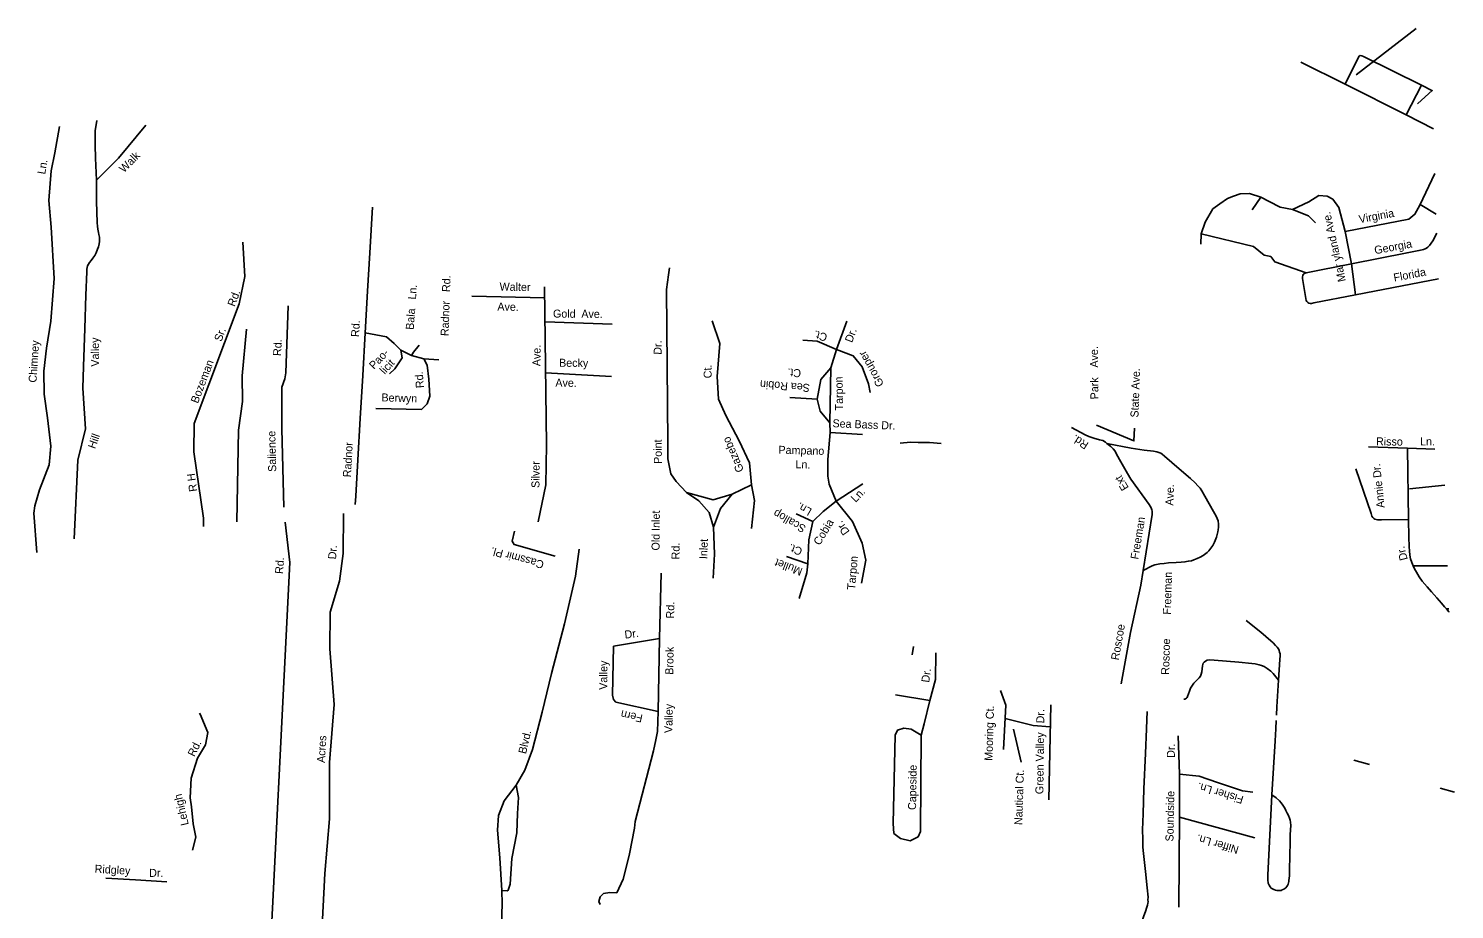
# Model space of a CAD drawing. Extents: x 2308163 to 2335412, y -96774 to 127732.
# Drawn here: x 2321661.2 to 2322026.5, y 52675.9 to 52901.5 of the extents above; entities that cross this region are included whole.
import ezdxf

# ---------------------------------------------------------------- set-up
doc = ezdxf.new("R2010")
doc.units = 0
doc.layers.add('Old_Level_10', color=7, linetype='Continuous')
doc.layers.add('Old_Level_35', color=7, linetype='Continuous')

msp = doc.modelspace()

# ---------------------------------------------------------------- linework, layer by layer
at = {"layer": 'Old_Level_10'}
for points in [[(2322016.66, 52901.47), (2322001.3, 52889.64)], [(2322020.83, 52885.72), (2322017.03, 52882.22)], [(2321944.49, 52799.11), (2321944.38, 52795.89), (2321934.83, 52799.93)], [(2321915.47, 52713.63), (2321913.5, 52722.08)]]:
    msp.add_lwpolyline(points, dxfattribs=at)
at = {"layer": 'Old_Level_35'}
for p, q in [((2321987.14, 52892.82), (2321998.45, 52887.22)), ((2321998.45, 52887.22), (2322014.14, 52879.35)), ((2322014.14, 52879.35), (2322018.07, 52886.93)), ((2322020.84, 52885.55), (2322018.07, 52886.93)), ((2322021.14, 52875.83), (2322014.14, 52879.35)), ((2322001.15, 52833.32), (2322000.08, 52841.23)), ((2322014.71, 52775.78), (2322014.44, 52794)), ((2321706, 52776.1), (2321703.58, 52793.06)), ((2321744.9, 52779.59), (2321745.02, 52781.74)), ((2321706.01, 52773.96), (2321706, 52776.1)), ((2321887.58, 52741.13), (2321887.87, 52743.25)), ((2321980.99, 52727.77), (2321981.38, 52734.62)), ((2321980.87, 52725.66), (2321980.99, 52727.77)), ((2321947.58, 52722.18), (2321947.67, 52724.47)), ((2321947.67, 52724.47), (2321947.75, 52726.6)), ((2321980.78, 52724.25), (2321980.69, 52722.14)), ((2321980.69, 52722.14), (2321980.56, 52719.06)), ((2321980.56, 52719.06), (2321979.74, 52705.27)), ((2322004.75, 52713.05), (2322000.7, 52714.08)), ((2322026.5, 52705.96), (2322022.86, 52706.99))]:
    msp.add_line(p, q, dxfattribs=at)
for points in [[(2322018.07, 52886.93), (2322003.18, 52894.3), (2322002.74, 52894.52), (2322002.37, 52894.58), (2322002.06, 52894.4), (2322001.93, 52894.14), (2321998.45, 52887.22)], [(2321678.62, 52862.63), (2321678.39, 52868.27), (2321678.28, 52871.58), (2321678.24, 52872.95), (2321678.3, 52875.27), (2321678.68, 52877.88)], [(2321667.96, 52869.61), (2321669.14, 52876.38)], [(2321691.28, 52876.77), (2321684.26, 52868.24), (2321678.62, 52862.63)], [(2321663.29, 52767.31), (2321662.56, 52777.37), (2321662.78, 52779.27), (2321664.03, 52783.34), (2321666.47, 52789.76), (2321666.95, 52794.5), (2321666.1, 52801.82), (2321665.19, 52807.88), (2321665.08, 52813.75), (2321665.76, 52819.59), (2321666.95, 52826.52), (2321667.8, 52837.43), (2321666.99, 52850.62), (2321666.43, 52857.45), (2321667.01, 52865.04), (2321667.96, 52869.61)], [(2321675.15, 52809.36), (2321675.28, 52814.94), (2321675.58, 52824.68), (2321675.85, 52833.23), (2321676.13, 52839.17), (2321676.13, 52839.87), (2321676.18, 52840.29), (2321676.28, 52840.74), (2321676.55, 52841.16), (2321676.82, 52841.53), (2321677.25, 52842.09), (2321677.71, 52842.7), (2321678.15, 52843.36), (2321678.5, 52844.04), (2321678.89, 52844.98), (2321679.09, 52845.61), (2321679.26, 52846.33), (2321679.35, 52846.98), (2321679.34, 52847.51), (2321679.34, 52848.04), (2321679.25, 52848.7), (2321679.15, 52849.23), (2321678.95, 52850.07), (2321678.84, 52850.83), (2321678.74, 52851.69), (2321678.62, 52857.25), (2321678.62, 52862.63)], [(2322017.62, 52856.24), (2322021.5, 52864.36)], [(2322000.08, 52841.23), (2321998.49, 52849.48), (2321996.84, 52855.63), (2321995.33, 52857.81), (2321993.89, 52858.52), (2321991.78, 52858.73), (2321989.2, 52857.09), (2321985.02, 52855.11), (2321981.85, 52855.75), (2321978.98, 52857.18), (2321976.9, 52858.31), (2321974.01, 52859.21), (2321971.62, 52859.16), (2321969.87, 52858.55), (2321968.39, 52857.94), (2321966.35, 52856.55), (2321964.59, 52855.29), (2321962.61, 52851.91), (2321961.58, 52848.89), (2321961.49, 52846.24)], [(2321745.02, 52781.74), (2321745.56, 52791.03), (2321746.18, 52801.65), (2321746.83, 52812.64), (2321747.46, 52823.56), (2321748.04, 52834.24), (2321748.65, 52844.04), (2321749.3, 52855.74)], [(2321976.9, 52858.31), (2321974.66, 52855.07)], [(2321998.49, 52849.48), (2322014.84, 52852.63), (2322016.35, 52853.9), (2322017.62, 52856.24)], [(2322021.83, 52853.92), (2322017.7, 52856.4)], [(2321985.02, 52855.11), (2321989.07, 52853.51), (2321990.87, 52851.73)], [(2321961.58, 52848.89), (2321975, 52845.64), (2321977.71, 52843.43), (2321979.43, 52843.11), (2321980.44, 52841.74), (2321988.54, 52838.89)], [(2322000.08, 52841.23), (2322014.35, 52844.07), (2322017.37, 52844.62), (2322018.19, 52844.79), (2322018.56, 52844.9), (2322019, 52845.09), (2322019.29, 52845.26), (2322019.64, 52845.5), (2322020.06, 52845.9), (2322020.53, 52846.48), (2322020.92, 52847.1), (2322021.99, 52849.06)], [(2321703.58, 52793.06), (2321703.64, 52800.31), (2321715.19, 52830.99), (2321716.58, 52838), (2321716.12, 52846.78)], [(2322001.15, 52833.32), (2321990.47, 52831.21), (2321989.83, 52831.09), (2321989.56, 52831.09), (2321989.22, 52831.17), (2321988.96, 52831.3), (2321988.66, 52831.55), (2321988.47, 52831.87), (2321987.56, 52837.46), (2321987.56, 52837.89), (2321987.63, 52838.21), (2321987.77, 52838.52), (2321987.89, 52838.66), (2321988.22, 52838.83), (2321988.54, 52838.89), (2322000.08, 52841.23)], [(2321836.58, 52760.75), (2321836.97, 52766.88), (2321836.67, 52773.75), (2321835.53, 52777.58), (2321832.93, 52780.56), (2321829.75, 52782.65), (2321827.13, 52785.45), (2321825.76, 52787.48), (2321824.99, 52791.3), (2321824.95, 52795.46), (2321824.67, 52834.64), (2321825.17, 52838.41), (2321825.41, 52840.21)], [(2322022.36, 52837.36), (2322013.09, 52835.59), (2322001.15, 52833.32)], [(2321791.76, 52775.12), (2321793.72, 52784.62), (2321793.89, 52794.9), (2321793.4, 52835.3)], [(2321726.57, 52778.9), (2321726.08, 52798.96), (2321726.09, 52809.61), (2321726.89, 52811.75), (2321727.12, 52813.27), (2321727.71, 52830.49)], [(2321774.79, 52832.93), (2321793.44, 52832.48)], [(2321793.51, 52826.33), (2321810.68, 52825.74)], [(2321846.43, 52784.6), (2321845.9, 52790.22), (2321843.21, 52795.91), (2321839.82, 52802.34), (2321837.98, 52806.56), (2321837.64, 52812.35), (2321838.29, 52820.81), (2321836.32, 52826.66)], [(2321868.11, 52780.43), (2321866.28, 52784.82), (2321865.99, 52786.82), (2321865.95, 52791.15), (2321866.55, 52797.99), (2321866.46, 52800.52), (2321866.76, 52814.59), (2321868.19, 52819.24), (2321870.79, 52826.55)], [(2321714.54, 52775.18), (2321714.96, 52798.62), (2321716.03, 52805.98), (2321715.9, 52812.58), (2321717.03, 52824.45)], [(2321747.46, 52823.56), (2321752.93, 52822.49), (2321754.86, 52820.8), (2321756.61, 52819.12), (2321756.9, 52817.12), (2321755, 52814.3), (2321753.69, 52813.08)], [(2321756.61, 52819.12), (2321759.27, 52817.76), (2321759.84, 52818.64), (2321761.31, 52820.42)], [(2321868.19, 52819.24), (2321863.2, 52821.4), (2321859.6, 52821.7)], [(2321868.19, 52819.24), (2321872.47, 52817.65), (2321874.72, 52814.86), (2321876.38, 52810.47), (2321876.84, 52808.29)], [(2321762.49, 52816.93), (2321763.34, 52815.27), (2321763.76, 52811.65), (2321763.97, 52807.31), (2321763.36, 52805.34), (2321761.87, 52803.95), (2321750.13, 52804.17)], [(2321759.27, 52817.76), (2321762.49, 52816.93), (2321766.28, 52816.62)], [(2321793.67, 52813.33), (2321810.57, 52812.37)], [(2321866.76, 52814.59), (2321864.13, 52811.62), (2321863.23, 52806.59), (2321864.03, 52803.49), (2321866.46, 52800.52)], [(2321675.15, 52809.36), (2321675.83, 52798.95), (2321673.81, 52790.93), (2321672.88, 52770.79)], [(2321863.23, 52806.59), (2321856.2, 52807.01)], [(2321866.55, 52797.99), (2321874.85, 52797.53)], [(2321928.35, 52799.3), (2321931.87, 52797.46), (2321932.8, 52797), (2321934.11, 52796.59), (2321935.52, 52796.19), (2321936.4, 52795.98), (2321937.08, 52795.59), (2321937.45, 52795.2)], [(2321894.97, 52795.25), (2321891.97, 52795.43), (2321889.13, 52795.45), (2321887.15, 52795.52), (2321884.53, 52795.3)], [(2321946.73, 52762.72), (2321949.08, 52776.99), (2321949.08, 52777.36), (2321949.03, 52777.85), (2321948.98, 52778.25), (2321948.91, 52778.5), (2321948.82, 52778.75), (2321948.26, 52779.62), (2321943.6, 52786.11), (2321942.76, 52787.51), (2321941.02, 52790.55), (2321939.94, 52792.45), (2321939.53, 52793.22), (2321939.04, 52793.85), (2321938.48, 52794.43), (2321937.45, 52795.2)], [(2321937.45, 52795.2), (2321943.67, 52794.05), (2321947.04, 52793.54), (2321949.4, 52793.23), (2321950.28, 52793.08), (2321950.77, 52792.94), (2321951.26, 52792.73), (2321951.64, 52792.49), (2321952.19, 52791.98), (2321955.99, 52788.69), (2321958.86, 52786.25), (2321960.08, 52785.15), (2321960.76, 52784.39), (2321961.31, 52783.75), (2321961.79, 52783.12), (2321962.51, 52781.72), (2321964.79, 52777.78), (2321965.45, 52776.59), (2321965.68, 52775.98), (2321965.92, 52775.39), (2321966.07, 52774.56), (2321966.06, 52773.76), (2321965.99, 52773.14), (2321965.9, 52772.57), (2321965.54, 52771.23), (2321965.04, 52769.96), (2321964.58, 52769.1), (2321964.12, 52768.42), (2321963.54, 52767.69), (2321963.16, 52767.32), (2321962.84, 52767.02), (2321962.1, 52766.51), (2321961.38, 52766.11), (2321960.58, 52765.73), (2321959.71, 52765.39), (2321959.16, 52765.19), (2321958.31, 52765.04), (2321957.42, 52764.89), (2321956.44, 52764.84), (2321955.16, 52764.76), (2321953.22, 52764.62), (2321952.15, 52764.52), (2321951.01, 52764.36), (2321949.77, 52764.14), (2321949.07, 52763.91), (2321946.73, 52762.72)], [(2322004.5, 52794.34), (2322014.44, 52794)], [(2322014.44, 52794), (2322021.46, 52793.76)], [(2322014.71, 52775.78), (2322007.82, 52775.69), (2322007.07, 52775.65), (2322006.82, 52775.66), (2322006.45, 52775.73), (2322006.1, 52775.82), (2322005.84, 52775.97), (2322005.54, 52776.26), (2322005.34, 52776.62), (2322005.18, 52777.26), (2322001.26, 52788.74)], [(2321829.75, 52782.65), (2321836.55, 52780.79), (2321841.47, 52782.25)], [(2321836.67, 52773.75), (2321838.46, 52778.56), (2321841.47, 52782.25), (2321846.43, 52784.6), (2321847.2, 52780.61), (2321846.41, 52773.41)], [(2321868.11, 52780.43), (2321874.95, 52784.88)], [(2322024.02, 52784.55), (2322015.01, 52783.64)], [(2321862.15, 52775.22), (2321864.77, 52777.83), (2321868.11, 52780.43), (2321872.27, 52775.23), (2321874.79, 52769.73), (2321875.72, 52765.36), (2321874.62, 52759.44)], [(2321722.28, 52647.3), (2321728.17, 52764.72), (2321726.92, 52775.07)], [(2321735.04, 52644.89), (2321737.12, 52685.14), (2321738.28, 52699.07), (2321738.32, 52713.51), (2321739.52, 52728.36), (2321738.41, 52742.6), (2321738.5, 52751.99), (2321740.84, 52759.93), (2321741.77, 52767), (2321741.9, 52777.3)], [(2321860.88, 52764.43), (2321861.09, 52770.56), (2321862.15, 52775.22), (2321857.88, 52777.17)], [(2322015.91, 52763.92), (2322015.56, 52764.75), (2322015.27, 52765.69), (2322015.1, 52766.58), (2322014.95, 52767.7), (2322014.85, 52768.77), (2322014.78, 52771.28), (2322014.71, 52775.78)], [(2321796.1, 52766.38), (2321785.59, 52769.36), (2321785.1, 52770.16), (2321785.66, 52772.8)], [(2321788.5, 52633.25), (2321786.64, 52636.46), (2321785.37, 52637.42), (2321782.53, 52653.88), (2321782.28, 52658.21), (2321782.09, 52663.97), (2321782.55, 52677.31), (2321782.41, 52680.72), (2321781.91, 52689.11), (2321781.37, 52696.2), (2321781.63, 52699.99), (2321783.07, 52703.74), (2321786.09, 52707.69), (2321788.32, 52711.54), (2321790.33, 52716.84), (2321792.76, 52726.44), (2321795.2, 52736.3), (2321798.52, 52749.02), (2321801.29, 52761.23), (2321802.24, 52768.12)], [(2321858.58, 52755.48), (2321860.62, 52762.09), (2321860.88, 52764.43), (2321855.34, 52766.24)], [(2322025.04, 52752.03), (2322025.01, 52752.08), (2322024.46, 52752.85), (2322023.98, 52753.42), (2322023.2, 52754.31), (2322021.97, 52755.65), (2322020.64, 52757.19), (2322019.54, 52758.47), (2322018.24, 52759.95), (2322017.48, 52761.07), (2322016.75, 52762.22), (2322016.27, 52763.11), (2322015.91, 52763.92)], [(2322024.67, 52763.92), (2322024.36, 52763.92), (2322015.91, 52763.92)], [(2321823.23, 52761.97), (2321822.86, 52745.25), (2321811.06, 52743.3), (2321810.83, 52730.74), (2321811.05, 52729.62), (2321811.68, 52728.94), (2321822.54, 52726.6), (2321822.86, 52745.25)], [(2321941.15, 52733.65), (2321943.47, 52746.85), (2321946.13, 52758.91), (2321946.73, 52762.72)], [(2321981.38, 52734.62), (2321981.76, 52739.93), (2321981.84, 52740.86), (2321981.82, 52741.33), (2321981.71, 52741.81), (2321981.56, 52742.24), (2321981.38, 52742.64), (2321981.08, 52743.07), (2321980.67, 52743.52), (2321980.05, 52744.16), (2321979.43, 52744.67), (2321976.86, 52746.86), (2321973.12, 52749.89)], [(2322024.46, 52752.85), (2322025.02, 52752.88)], [(2321893.63, 52741.6), (2321893.54, 52734.79), (2321892.1, 52729.42), (2321883.32, 52730.86)], [(2321957.18, 52729.72), (2321957.38, 52729.75), (2321957.6, 52729.86), (2321957.82, 52730), (2321957.98, 52730.18), (2321958.14, 52730.42), (2321958.34, 52731.11), (2321958.61, 52731.79), (2321958.88, 52732.53), (2321959.34, 52733.33), (2321959.72, 52733.83), (2321960.43, 52734.55), (2321961.07, 52735.23), (2321961.4, 52735.66), (2321961.61, 52736.16), (2321961.8, 52736.77), (2321961.88, 52737.52), (2321961.98, 52738.26), (2321962.04, 52738.61), (2321962.12, 52738.92), (2321962.36, 52739.24), (2321962.73, 52739.51), (2321963.12, 52739.69), (2321963.62, 52739.8), (2321964.93, 52739.7), (2321971.24, 52739.18), (2321974.6, 52738.85), (2321975.47, 52738.76), (2321976.48, 52738.56), (2321977.09, 52738.35), (2321977.78, 52738.08), (2321978.55, 52737.58), (2321979.47, 52736.87), (2321980.05, 52736.3), (2321981.38, 52734.62)], [(2321910.23, 52731.94), (2321911.59, 52728.24), (2321910.95, 52716.81)], [(2321892.1, 52729.42), (2321890.63, 52723.43), (2321889.9, 52720.55), (2321889.68, 52695.88), (2321889.13, 52694.51), (2321887.08, 52693.45), (2321884.58, 52694.04), (2321882.86, 52695.36), (2321882.69, 52697.88), (2321883.22, 52720.53), (2321883.77, 52721.77), (2321885.43, 52722.35), (2321887.31, 52722.03), (2321889.9, 52720.55)], [(2321922.6, 52703.93), (2321923.05, 52728.27)], [(2321705, 52726.18), (2321705.14, 52725.86), (2321707.11, 52721.24), (2321706.54, 52718.06), (2321704.45, 52714.64), (2321702.9, 52709.51), (2321702.57, 52704.5), (2321702.95, 52702.21), (2321703.41, 52697.78), (2321704.05, 52694.41), (2321703.18, 52691.09)], [(2321822.54, 52726.6), (2321822.36, 52721.5), (2321821.89, 52719.3), (2321821.34, 52716.5), (2321816.59, 52698.44), (2321816.4, 52696.68), (2321815.12, 52690.12), (2321814.89, 52689.01), (2321813.53, 52683.63), (2321811.9, 52680.15), (2321810.13, 52680.21), (2321808.49, 52679.94), (2321807.61, 52679.12), (2321807.3, 52677.95), (2321807.67, 52677.15)], [(2321911.39, 52724.75), (2321918.59, 52722.97), (2321922.95, 52722.67)], [(2321946.34, 52672.02), (2321946.49, 52672.55), (2321946.7, 52673.48), (2321946.9, 52674.29), (2321947.31, 52675.4), (2321947.65, 52676.46), (2321947.85, 52677.02), (2321947.92, 52677.46), (2321947.99, 52677.82), (2321947.94, 52678.39), (2321948.02, 52679.01), (2321947.77, 52681.46), (2321947.37, 52685.6), (2321946.85, 52690.24), (2321946.64, 52691.81), (2321946.63, 52693.87), (2321946.57, 52696.31), (2321946.72, 52700.37), (2321946.94, 52706.74), (2321947.34, 52715.79), (2321947.58, 52722.18)], [(2321956.04, 52710.56), (2321955.71, 52720.38)], [(2321955.92, 52676.48), (2321956.06, 52699.55), (2321956.04, 52710.56)], [(2321956.04, 52710.56), (2321961.06, 52709.99), (2321965.78, 52708.37), (2321972.21, 52706.29), (2321974.85, 52705.93)], [(2321786.09, 52707.69), (2321786.76, 52704.55), (2321786.49, 52700.5), (2321786.32, 52695.53), (2321785.05, 52688.9), (2321784.56, 52682.37), (2321784.11, 52680.82), (2321783.85, 52680.7), (2321782.41, 52680.72)], [(2321979.74, 52705.27), (2321978.67, 52684.66), (2321978.68, 52683.44), (2321978.75, 52682.63), (2321978.98, 52682.09), (2321979.24, 52681.71), (2321979.57, 52681.37), (2321979.84, 52681.19), (2321980.21, 52680.99), (2321980.62, 52680.85), (2321981.07, 52680.73), (2321981.46, 52680.71), (2321981.7, 52680.72), (2321982.06, 52680.78), (2321982.34, 52680.88), (2321982.75, 52681.05), (2321983.04, 52681.24), (2321983.28, 52681.42), (2321983.55, 52681.73), (2321983.74, 52682.03), (2321983.87, 52682.34), (2321983.98, 52682.74), (2321984.04, 52683.04), (2321984.1, 52683.42), (2321984.16, 52683.84), (2321984.24, 52684.58), (2321984.25, 52685.47), (2321984.27, 52686.02), (2321984.38, 52693.22), (2321984.42, 52695.03), (2321984.5, 52696.31), (2321984.54, 52697.4), (2321984.49, 52698.28), (2321984.37, 52698.73), (2321984.22, 52699.28), (2321983.97, 52699.95), (2321983.67, 52700.55), (2321983.33, 52701.24), (2321983, 52701.81), (2321982.49, 52702.64), (2321982.06, 52703.22), (2321981.69, 52703.67), (2321980.81, 52704.44), (2321979.74, 52705.27)], [(2321956.06, 52699.55), (2321975.38, 52694.24)], [(2321681, 52683.94), (2321688.6, 52683.5), (2321696.65, 52682.94)]]:
    msp.add_lwpolyline(points, dxfattribs=at)

# ---------------------------------------------------------------- texts
at = {"layer": 'Old_Level_10'}
for s, height, rotation, p in [('Walk', 2.051, 45.3872, (2321685.65, 52864.4)), ('Ln.', 2.051, 80.1858, (2321665.45, 52864.03)), ('Mar yland Ave.', 2.0505, 102.8292, (2321998.69, 52836.85)), ('Virginia', 2.051, 10.4931, (2322002.18, 52851.62)), ('Georgia', 2.051, 10.4813, (2322006.16, 52843.66)), ('Radnor   Rd.', 2.0505, 88.1523, (2321768.8, 52822.69)), ('Florida', 2.051, 11.0089, (2322011.09, 52836.65)), ('Bozeman       Sr.        Rd.', 2.0505, 69.1948, (2321704.58, 52805.33)), ('Bala   Ln.', 2.051, 85.7542, (2321759.86, 52824.27)), ('Walter', 2.051, 358.7381, (2321781.85, 52834.39)), ('Ave.', 2.051, 358.7381, (2321781.29, 52829.27)), ('Rd.', 2.051, 86.9357, (2321745.86, 52822.44)), ('Gold', 2.051, 359.4093, (2321795.55, 52827.46)), ('Ave.', 2.051, 359.4093, (2321802.81, 52827.4)), ('Valley', 2.051, 90.4143, (2321679.27, 52814.9)), ('Ct.', 2.051, 163.8283, (2321866.01, 52823.24)), ('Dr.', 2.051, 69.3849, (2321872.16, 52820.89)), ('Chimney', 2.051, 86.2486, (2321663.23, 52810.75)), ('Rd.', 2.051, 87.6086, (2321725.9, 52817.58)), ('Pao-', 2.051, 46.9069, (2321749.72, 52814.05)), ('Ave.', 2.051, 89.5229, (2321792.34, 52815)), ('Dr.', 2.051, 89.4605, (2321823.38, 52817.94)), ('Grouper', 2.051, 119.423, (2321880.42, 52810.41)), ('Ave.', 2.051, 90.5704, (2321935.21, 52814.65)), ('licit', 2.051, 46.9069, (2321752.44, 52812.78)), ('Becky', 2.051, 359.3952, (2321797.11, 52814.87)), ('Ct.', 2.051, 91.0081, (2321836.22, 52811.92)), ('Rd.', 2.051, 94.3165, (2321762.5, 52809.46)), ('Ave.', 2.051, 359.3952, (2321796.16, 52809.76)), ('       Sea Robin ', 2.0505, 175.7151, (2321866.74, 52810.02)), ('Ct.', 2.051, 175.7151, (2321859.18, 52814.18)), ('Tarpon', 2.051, 90.9688, (2321869.88, 52803.68)), ('Park', 2.051, 90.5704, (2321935.29, 52806.52)), ('State Ave.', 2.051, 88.0247, (2321945.52, 52801.84)), ('Berwyn', 2.051, 358.1695, (2321751.59, 52806)), ('Sea Bass Dr.', 2.0505, 357.7622, (2321867.13, 52799.38)), ('Hill ', 2.051, 70.5702, (2321678.27, 52793.7)), ('Salience', 2.051, 91.3925, (2321724.66, 52787.97)), ('Gazebo', 2.051, 113.0823, (2321844.52, 52788.34)), ('Rd.', 2.051, 147.5672, (2321932.96, 52795.31)), ('Risso', 2.051, 359.2312, (2322006.39, 52794.75)), ('Ln.', 2.051, 359.7872, (2322017.69, 52794.73)), ('Radnor', 2.051, 86.7192, (2321743.76, 52786.52)), ('Point', 2.051, 90.4182, (2321823.45, 52790)), ('Pampano ', 2.051, 358.5677, (2321853.3, 52792.58)), ('Silver', 2.051, 89.5225, (2321792.08, 52783.82)), ('Ln.', 2.051, 358.5677, (2321857.65, 52788.88)), ('Annie Dr.', 2.051, 96.0826, (2322008.63, 52778.79)), ('R H', 2.051, 97.6871, (2321704.4, 52783)), ('Ext', 2.051, 120.8787, (2321943.13, 52783.9)), ('Ln.', 2.051, 45.7345, (2321873.07, 52779.98)), ('Ave.', 2.051, 88.3651, (2321954.48, 52779.28)), ('Ln.', 2.051, 150.3852, (2321862.06, 52778.38)), ('Old Inlet', 2.051, 89.4837, (2321822.85, 52767.8)), ('Scallop ', 2.051, 150.3852, (2321860.55, 52774)), ('Cobia', 2.051, 58.9524, (2321863.89, 52768.96)), ('Dr.', 2.051, 125.5361, (2321871.64, 52772.64)), ('Freeman', 2.051, 80.6561, (2321945.49, 52765.42)), ('Dr.', 2.051, 85.9893, (2321739.97, 52765.5)), ('Cassmir Pl.', 2.0505, 164.8672, (2321793.41, 52765.06)), ('Rd.', 2.051, 89.4837, (2321827.96, 52765.52)), ('Inlet', 2.051, 88.0247, (2321835.06, 52765.58)), ('Ct.', 2.051, 159.1202, (2321859.64, 52768.35)), ('Dr.', 2.051, 104.7581, (2322014.54, 52765.55)), ('Rd.', 2.051, 85.8938, (2321726.38, 52761.75)), ('Mullet', 2.051, 159.1202, (2321859.68, 52763.19)), ('Tarpon', 2.051, 84.9637, (2321872.91, 52757.67)), ('Freeman', 2.051, 88.3651, (2321953.83, 52751.35)), ('Rd.', 2.051, 89.1148, (2321826.58, 52750.4)), ('Dr.', 2.051, 7.317, (2321814.01, 52745.23)), ('Roscoe', 2.051, 79.9866, (2321940.48, 52739.61)), ('Brook', 2.051, 89.1145, (2321826.36, 52735.99)), ('Roscoe ', 2.051, 88.3651, (2321953.39, 52735.95)), ('Valley', 2.051, 89.346, (2321809.43, 52732.13)), ('Dr.', 2.051, 82.1293, (2321891.92, 52733.9)), ('Valley', 2.051, 89.1134, (2321826.13, 52721.05)), ('Mooring Ct.', 2.0505, 88.2612, (2321908.13, 52713.93)), ('Fern', 2.051, 167.8001, (2321818.68, 52725.73)), ('Green Valley   Dr.', 2.0505, 89.2964, (2321921.17, 52705.4)), ('Acres', 2.051, 86.6331, (2321737.1, 52713.38)), ('Blvd.', 2.051, 76.5539, (2321788.62, 52715.59)), ('Rd.', 2.051, 63.6699, (2321703.69, 52714.84)), ('Dr.', 2.051, 89.6449, (2321954.86, 52714.71)), ('Capeside', 2.051, 89.1012, (2321888.55, 52701.35)), ('Nautical Ct.', 2.0505, 88.0247, (2321915.74, 52697.48)), ('Lehigh', 2.051, 103.2557, (2321702.27, 52697.63)), ('Soundside ', 2.051, 88.8548, (2321954.49, 52693.28)), ('Fisher Ln.', 2.051, 162.943, (2321972.63, 52704.85)), ('Niffer Ln.', 2.051, 163.6322, (2321971.41, 52692.01)), ('Ridgley', 2.051, 356.7432, (2321678.1, 52685.3)), ('Dr.', 2.051, 359.0282, (2321692.08, 52684.25))]:
    msp.add_text(s, height=height, rotation=rotation, dxfattribs=at).set_placement(p)

doc.saveas('drawing.dxf')
